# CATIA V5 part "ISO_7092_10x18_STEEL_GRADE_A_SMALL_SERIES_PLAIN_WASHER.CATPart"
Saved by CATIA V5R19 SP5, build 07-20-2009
Part number: ISO 7092 WASHER 10x18 STEEL GRADE A PLAIN SMALL SERIES
Publications: "Mating Face", "Axis"
Bounding box of the stored display mesh (mm): x 0 to 1, y -9 to 9, z -9 to 9
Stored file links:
  Z:\UA\ATLAS\atlascar\ServoPiloto\dir\suportePotenciometro\ISO_7092_10x18_STEEL_GRADE_A_SMALL_SERIES_PLAIN_WASHER.CATPart
  Z:\programs_vbox\Dassault Systemes\B19\intel_a\startup\components\MechanicalStandardParts\ISO_Standards\Design_Tables\ISO_7092_PLAIN_WASHER_GRADE_A_SMALL_SERIES.txt
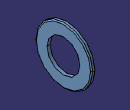
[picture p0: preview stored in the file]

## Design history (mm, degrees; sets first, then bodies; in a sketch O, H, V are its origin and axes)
Parameters
  d1_inside_dia = 10.5 mm
  d2_outside_dia = 18 mm
  h_max = 1 mm
  Nominal_dia = 10 mm
Body1 "PartBody" (main body)
  Sketch1 on yz-plane, origin (0, 0, 0), H (0, 1, 0), V (0, 0, 1)
    circle A1 centre (0, 0) radius 9
    circle A2 centre (0, 0) radius 5.25
    radius A1 = 9 {= d2_outside_dia /2}
    radius A2 = 5.25 {= d1_inside_dia /2}
  Pad1: profile Sketch1, direction (1, 0, 0), length 1 {= h_max}
  Chamfer1: length 0.375 {= 0.375*h_max}, angle 37.5, on edge [face of Pad1 | face of Pad1]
